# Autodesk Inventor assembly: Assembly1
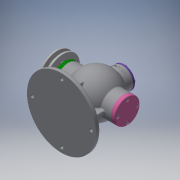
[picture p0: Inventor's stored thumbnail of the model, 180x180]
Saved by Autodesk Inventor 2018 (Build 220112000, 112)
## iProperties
Created: 2020-08
Part Number: Assembly1
Document SubType Name: Assembly
Designer: Administrator
Author: Administrator
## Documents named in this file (18)
- C:\Users\Administrator\Desktop\700806V1053\Assembly1.iam
- C:\Users\Administrator\Desktop\700806V1053\700806V1053.ipt
- C:\Users\Administrator\Desktop\700806V1053\V-벨트풀리.ipt
- C:\Users\Administrator\Desktop\700806V1053\너트 M8.ipt
- C:\Users\Administrator\Desktop\700806V1053\뒤커버.ipt
- C:\Users\Administrator\Desktop\700806V1053\멈춤링 15x1.ipt
- C:\Users\Administrator\Desktop\700806V1053\멈춤링 35x1.6.ipt
- 멈춤링 35x1.6.ipt
- C:\Users\Administrator\Desktop\700806V1053\베어링 6202.ipt
- 베어링 6202.ipt
- C:\Users\Administrator\Desktop\700806V1053\볼트 M4.ipt
- C:\Users\Administrator\Desktop\700806V1053\상부커버.ipt
- C:\Users\Administrator\Desktop\700806V1053\슬라이드.ipt
- C:\Users\Administrator\Desktop\700806V1053\앞커버.ipt
- C:\Users\Administrator\Desktop\700806V1053\오일 실 15 30 7.ipt
- C:\Users\Administrator\Desktop\700806V1053\칼라.ipt
- C:\Users\Administrator\Desktop\700806V1053\키 3x3x12.ipt
- C:\Users\Administrator\Desktop\700806V1053\편심축.ipt
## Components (2 placed, 2 different names)
1. 700806V1053:1 — Insert:1, Insert:2, Insert:3, Insert:4, Insert:19, Insert:20
2. V-벨트풀리:1 — Insert:27, Mate:3, Angle:1, Insert:28
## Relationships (10: Insert 8, Mate 1, Angle 1)
- Insert:1: 700806V1053:1
- Insert:2: 700806V1053:1
- Insert:3: 700806V1053:1
- Insert:4: 700806V1053:1
- Insert:19: 700806V1053:1
- Insert:20: 700806V1053:1
- Insert:27: V-벨트풀리:1
- Mate:3: V-벨트풀리:1
- Angle:1: V-벨트풀리:1
- Insert:28: V-벨트풀리:1
